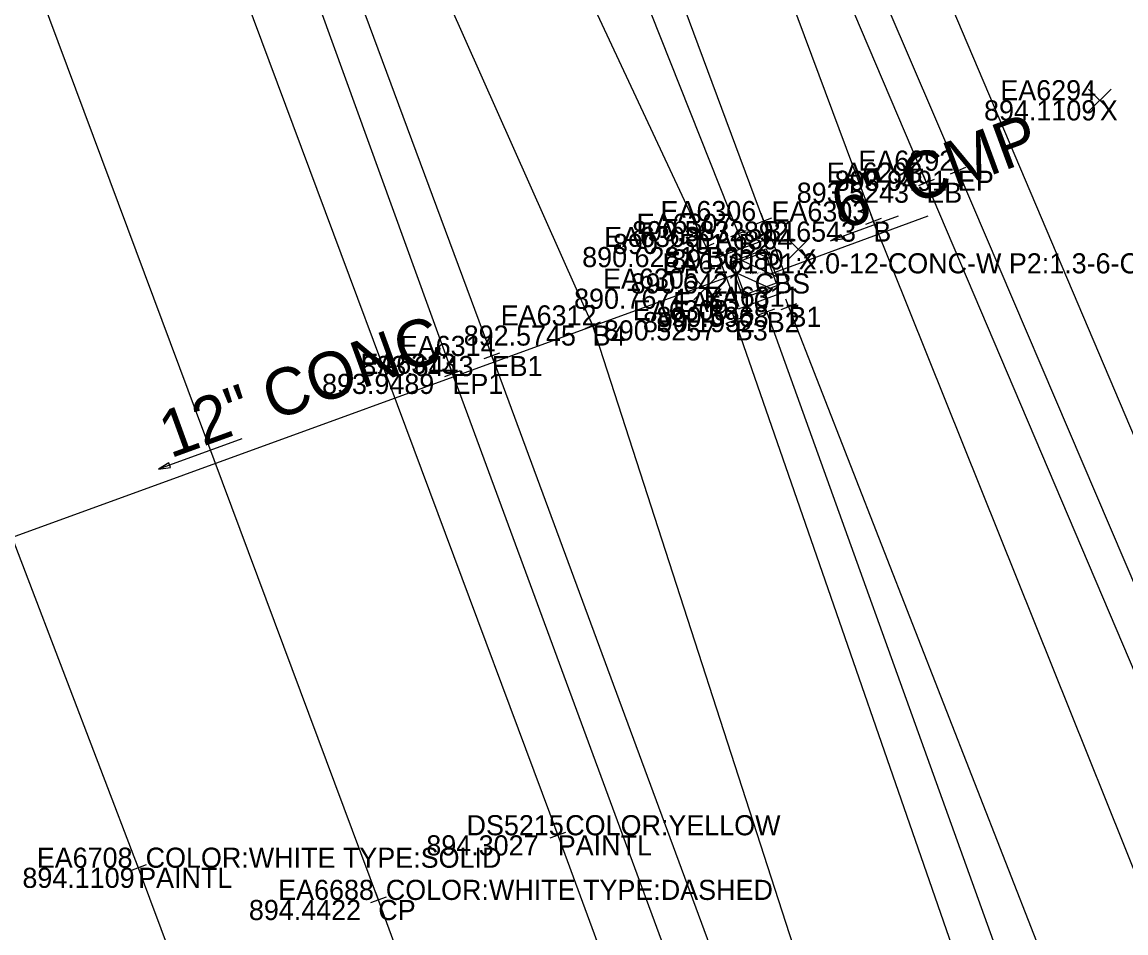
# Model space of a CAD drawing. Extents: x 179044 to 189691, y 286531 to 301257.
# Drawn here: x 180258 to 180323.8, y 300464 to 300518.4 of the extents above; entities that cross this region are included whole.
import ezdxf

# ---------------------------------------------------------------- set-up
doc = ezdxf.new("R2010")
doc.units = 0
for name, color, linetype in [('Default', 7, 'Continuous'), ('DR_X_Cells', 7, 'Continuous'), ('DR_X_Storm_Sewer', 7, 'Continuous'), ('DR_X_Text', 7, 'Continuous'), ('GK_Drainage_Nodes', 7, 'Continuous'), ('PM_X_Channelizing_Line', 7, 'Continuous'), ('PV_X_COP', 7, 'Continuous'), ('PV_X_EOP', 7, 'Continuous'), ('PV_X_Shoulder_Aggregate', 7, 'Continuous'), ('SV_X_Break_Lines', 7, 'Continuous'), ('SV_X_Random_Point', 7, 'Continuous'), ('SV_X_Shot_Marker', 7, 'Continuous'), ('SV_X_Text_Comment', 7, 'Continuous'), ('SV_X_Text_Description', 7, 'Continuous'), ('SV_X_Text_Elevation', 7, 'Continuous'), ('SV_X_Text_Name', 7, 'Continuous')]:
    doc.layers.add(name, color=color, linetype=linetype)

msp = doc.modelspace()

# ---------------------------------------------------------------- linework, layer by layer
at = {"layer": 'Default'}
for points in [[(180269.952, 300577.657), (180266.311, 300570.1), (180263.372, 300560.932), (180262.77, 300549.441), (180266.986, 300531.433), (180289.954, 300469.854), (180324.352, 300376.444), (180360.496, 300279.469), (180373.081, 300245.703)], [(180416.572, 300274.568), (180407.378, 300298.488), (180397.255, 300322.68), (180377.671, 300368.278), (180338.823, 300459.544), (180302.212, 300545.776), (180296.008, 300558.581), (180288.956, 300567.583), (180278.848, 300574.029), (180270.227, 300577.552)]]:
    msp.add_lwpolyline(points, dxfattribs=at)
at = {"layer": 'DR_X_Cells'}
for p, q in [((180300.732, 300504.228), (180302.991, 300503.187)), ((180300.732, 300504.228), (180302.991, 300503.187)), ((180301.794, 300504.62), (180302.6, 300504.248)), ((180301.794, 300504.62), (180302.6, 300504.248)), ((180300.44, 300503.482), (180302.614, 300502.48)), ((180300.44, 300503.482), (180302.614, 300502.48)), ((180300.831, 300502.421), (180301.552, 300502.088)), ((180300.831, 300502.421), (180301.552, 300502.088))]:
    msp.add_line(p, q, dxfattribs=at)
for points in [[(180302.691, 300505.506), (180303.844, 300502.378), (180300.717, 300501.225), (180299.564, 300504.352)], [(180302.691, 300505.506), (180303.844, 300502.378), (180300.717, 300501.225), (180299.564, 300504.352)], [(180302.383, 300504.837), (180303.175, 300502.687), (180301.025, 300501.894), (180300.232, 300504.044)], [(180302.383, 300504.837), (180303.175, 300502.687), (180301.025, 300501.894), (180300.232, 300504.044)], [(180302.296, 300504.65), (180302.988, 300502.773), (180301.112, 300502.081), (180300.42, 300503.958)], [(180302.296, 300504.65), (180302.988, 300502.773), (180301.112, 300502.081), (180300.42, 300503.958)]]:
    msp.add_lwpolyline(points, close=True, dxfattribs=at)
at = {"layer": 'DR_X_Storm_Sewer'}
for p, q in [((180302.704, 300503.365), (180312.049, 300506.806)), ((180300.704, 300503.365), (180226.568, 300476.391))]:
    msp.add_line(p, q, dxfattribs=at)
at = {"layer": 'DR_X_Text'}
for p, q in [((180310.249, 300506.782), (180306.226, 300505.301)), ((180271.105, 300493.5), (180266.14, 300491.694))]:
    msp.add_line(p, q, dxfattribs=at)
for points in [[(180306.831, 300505.684), (180306.935, 300505.403), (180306.226, 300505.301)], [(180266.849, 300491.792), (180266.746, 300492.074), (180266.14, 300491.694)]]:
    msp.add_lwpolyline(points, close=True, dxfattribs=at)
at = {"layer": 'GK_Drainage_Nodes'}
for p, q in [((180301.358, 300504.304), (180301.358, 300504.304)), ((180301.358, 300504.304), (180301.358, 300504.304)), ((180301.704, 300503.365), (180301.704, 300503.365)), ((180301.704, 300503.365), (180301.704, 300503.365)), ((180301.704, 300503.365), (180301.704, 300503.365)), ((180301.704, 300503.365), (180301.704, 300503.365)), ((180301.704, 300503.365), (180301.704, 300503.365)), ((180301.704, 300503.365), (180301.704, 300503.365)), ((180302.642, 300503.711), (180302.642, 300503.711)), ((180302.642, 300503.711), (180302.642, 300503.711)), ((180303.268, 300503.942), (180303.268, 300503.942)), ((180303.268, 300503.942), (180303.268, 300503.942)), ((180300.14, 300502.789), (180300.14, 300502.789)), ((180300.14, 300502.789), (180300.14, 300502.789)), ((180300.766, 300503.019), (180300.766, 300503.019)), ((180300.766, 300503.019), (180300.766, 300503.019)), ((180302.05, 300502.427), (180302.05, 300502.427)), ((180302.05, 300502.427), (180302.05, 300502.427))]:
    msp.add_line(p, q, dxfattribs=at)
at = {"layer": 'PM_X_Channelizing_Line'}
msp.add_lwpolyline([(180190.445, 300582.496), (180201.741, 300580.903), (180210.797, 300577.931), (180219.101, 300571.651), (180228.235, 300559.496), (180237.94, 300538.543), (180264.924, 300467.918), (180293.4, 300391.707), (180324.643, 300308.043), (180350.475, 300238.896)], dxfattribs=at)
at = {"layer": 'PV_X_COP'}
msp.add_lwpolyline([(180246.716, 300553.114), (180279.248, 300465.999), (180313.722, 300372.324), (180349.437, 300276.58), (180362.146, 300242.511)], dxfattribs=at)
at = {"layer": 'PV_X_EOP'}
for points in [[(180275.541, 300570.539), (180270.388, 300566.454), (180267.273, 300561.588), (180266.459, 300554.084), (180265.761, 300546.765), (180283.67, 300497.374), (180310.435, 300424.792), (180336.457, 300355.213), (180379.468, 300239.43)], [(180275.541, 300570.539), (180281.08, 300569.395), (180286.302, 300565.407), (180291.485, 300559.019), (180299.83, 300542.045), (180313.822, 300509.489), (180346.033, 300434.084), (180370.964, 300374.351), (180403.471, 300297.797), (180418.39, 300258.269)]]:
    msp.add_lwpolyline(points, dxfattribs=at)
at = {"layer": 'PV_X_Shoulder_Aggregate'}
for points in [[(180276.015, 300565.593), (180281.288, 300566.161), (180286.068, 300563.144), (180298.579, 300540.14), (180311.937, 300508.777), (180343.813, 300433.852), (180369.171, 300373.38), (180401.131, 300296.715), (180416.281, 300257.534)], [(180276.015, 300565.593), (180272.424, 300562.362), (180270.301, 300554.787), (180269.122, 300543.981), (180286.011, 300498.44), (180312.867, 300425.83), (180338.723, 300356.477), (180381.308, 300240.575)]]:
    msp.add_lwpolyline(points, dxfattribs=at)
at = {"layer": 'SV_X_Break_Lines'}
for points in [[(180285.869, 300558.023), (180297.684, 300536.245), (180308.778, 300506.456), (180338.649, 300432.1), (180367.2, 300369.993), (180410.141, 300254.681)], [(180281.085, 300555.439), (180289.69, 300533.513), (180300.73, 300505.723)], [(180284.601, 300552.482), (180292.195, 300533.463), (180302.232, 300506.484)], [(180278.676, 300551.659), (180285.337, 300533.721), (180298.804, 300504.938)], [(180274.364, 300549.595), (180277.806, 300532.178), (180292.031, 300500.259), (180315.947, 300426.336), (180343.875, 300357.803), (180387.064, 300242.808)], [(180303.72, 300501.373), (180331.456, 300430.396), (180357.818, 300364.306), (180401.637, 300249.805)], [(180302.421, 300501.058), (180327.985, 300430.042), (180355.523, 300363.079), (180398.147, 300248.566)], [(180300.517, 300500.565), (180325.39, 300428.896), (180352.275, 300361.992), (180395.375, 300246.26)]]:
    msp.add_lwpolyline(points, dxfattribs=at)
at = {"layer": 'SV_X_Random_Point'}
for p, q in [((180321.621, 300513.019), (180322.954, 300514.355)), ((180321.621, 300514.355), (180322.954, 300513.019)), ((180303.644, 300504.131), (180304.977, 300505.466)), ((180303.644, 300505.466), (180304.977, 300504.131)), ((180298.065, 300501.787), (180299.398, 300503.122)), ((180298.065, 300503.122), (180299.398, 300501.787))]:
    msp.add_line(p, q, dxfattribs=at)
at = {"layer": 'SV_X_Shot_Marker'}
for p, q in [((180313.625, 300509.948), (180314.02, 300509.03)), ((180314.282, 300509.686), (180313.363, 300509.291)), ((180313.822, 300509.489), (180313.822, 300509.489)), ((180312.397, 300508.973), (180311.477, 300508.581)), ((180311.741, 300509.237), (180312.133, 300508.317)), ((180311.937, 300508.777), (180311.937, 300508.777)), ((180302.701, 300506.658), (180301.764, 300506.309)), ((180302.058, 300506.952), (180302.407, 300506.015)), ((180309.247, 300506.63), (180308.31, 300506.281)), ((180308.604, 300506.924), (180308.953, 300505.987)), ((180300.545, 300506.187), (180300.915, 300505.258)), ((180302.232, 300506.484), (180302.232, 300506.484)), ((180308.778, 300506.456), (180308.778, 300506.456)), ((180298.592, 300505.391), (180299.015, 300504.486)), ((180301.195, 300505.907), (180300.265, 300505.538)), ((180300.73, 300505.723), (180300.73, 300505.723)), ((180299.256, 300505.15), (180298.351, 300504.727)), ((180298.804, 300504.938), (180298.804, 300504.938)), ((180302.251, 300501.529), (180302.59, 300500.588)), ((180304.186, 300501.555), (180303.254, 300501.191)), ((180303.538, 300501.839), (180303.902, 300500.908)), ((180303.72, 300501.373), (180303.72, 300501.373)), ((180291.828, 300500.716), (180292.235, 300499.803)), ((180300.989, 300500.729), (180300.045, 300500.401)), ((180300.353, 300501.038), (180300.681, 300500.093)), ((180302.891, 300501.228), (180301.95, 300500.889)), ((180302.421, 300501.058), (180302.421, 300501.058)), ((180292.488, 300500.463), (180291.575, 300500.056)), ((180292.031, 300500.259), (180292.031, 300500.259)), ((180300.517, 300500.565), (180300.517, 300500.565)), ((180285.837, 300498.909), (180286.185, 300497.971)), ((180286.48, 300498.614), (180285.542, 300498.266)), ((180286.011, 300498.44), (180286.011, 300498.44)), ((180284.14, 300497.544), (180283.2, 300497.203)), ((180283.5, 300497.844), (180283.84, 300496.904)), ((180283.67, 300497.374), (180283.67, 300497.374)), ((180290.422, 300470.028), (180289.485, 300469.679)), ((180289.779, 300470.322), (180290.129, 300469.385)), ((180289.954, 300469.854), (180289.954, 300469.854)), ((180265.391, 300468.097), (180264.457, 300467.74)), ((180264.746, 300468.385), (180265.103, 300467.451)), ((180264.924, 300467.918), (180264.924, 300467.918)), ((180279.073, 300466.467), (180279.423, 300465.53)), ((180279.717, 300466.174), (180278.78, 300465.824)), ((180279.248, 300465.999), (180279.248, 300465.999))]:
    msp.add_line(p, q, dxfattribs=at)

# ---------------------------------------------------------------- texts
at = {"layer": 'DR_X_Text'}
for s, rotation, p in [('6" CMP', 20.21069, (180306.926, 300505.932)), ('12" CONC', 19.99419, (180266.842, 300492.322))]:
    msp.add_text(s, height=2.8, rotation=rotation, dxfattribs=at).set_placement(p)
at = {"layer": 'SV_X_Text_Comment'}
for s, height, p in [('X', 1.2, (180322.288, 300512.487)), ('EP', 1.2, (180313.822, 300508.289)), ('EB', 1.2, (180311.937, 300507.577)), ('B1', 1.2, (180302.232, 300505.284)), ('B', 1.2, (180308.778, 300505.256)), ('B2', 1.2, (180300.73, 300504.523)), ('B3', 1.2, (180298.804, 300503.738)), ('X', 1.2, (180304.31, 300503.598)), ('P1=2.0-12-CONC-W P2=1.3-6-CMP-E', 0.06, (180301.704, 300503.305)), ('CBS', 1.2, (180301.704, 300502.165)), ('X', 1.2, (180298.732, 300501.254)), ('B1', 1.2, (180303.72, 300500.173)), ('B2', 1.2, (180302.421, 300499.858)), ('B4', 1.2, (180292.031, 300499.059)), ('B3', 1.2, (180300.517, 300499.365)), ('EB1', 1.2, (180286.011, 300497.24)), ('EP1', 1.2, (180283.67, 300496.174)), ('PAINTL', 1.2, (180289.954, 300468.654)), ('PAINTL', 1.2, (180264.924, 300466.718)), ('CP', 1.2, (180279.248, 300464.799))]:
    msp.add_text(s, height=height, dxfattribs=at).set_placement(p)
at = {"layer": 'SV_X_Text_Description'}
for s, height, p in [(' P1:2.0-12-CONC-W P2:1.3-6-CMP-E', 1.2, (180301.704, 300503.365)), ('P1= 2.0-12-CONC-W  P2=1.3-6-CMP-E', 0.06, (180301.704, 300503.365)), (' COLOR:YELLOW', 1.2, (180289.954, 300469.854)), (' COLOR:WHITE TYPE:SOLID', 1.2, (180264.924, 300467.918)), (' COLOR:WHITE TYPE:DASHED', 1.2, (180279.248, 300465.999))]:
    msp.add_text(s, height=height, dxfattribs=at).set_placement(p)
at = {"layer": 'SV_X_Text_Elevation'}
for s, height, p in [('894.1109', 1.2, (180315.382, 300512.487)), ('893.9491', 1.2, (180306.475, 300508.289)), ('893.5243', 1.2, (180304.209, 300507.577)), ('890.5832', 1.2, (180294.39, 300505.284)), ('892.6543', 1.2, (180301.05, 300505.256)), ('890.2501', 1.2, (180293.241, 300504.523)), ('890.6281', 1.2, (180291.409, 300503.738)), ('891.0080', 1.2, (180296.734, 300503.598)), ('890.6421', 1.2, (180294.299, 300502.165)), ('890.64', 0.06, (180301.416, 300503.305)), ('890.7674', 1.2, (180290.927, 300501.254)), ('890.5968', 1.2, (180295.84, 300500.173)), ('890.1932', 1.2, (180295.033, 300499.858)), ('892.5745', 1.2, (180284.341, 300499.059)), ('890.5257', 1.2, (180292.703, 300499.365)), ('893.6443', 1.2, (180278.235, 300497.24)), ('893.9489', 1.2, (180275.894, 300496.174)), ('894.3027', 1.2, (180282.112, 300468.654)), ('894.1109', 1.2, (180258.019, 300466.718)), ('894.4422', 1.2, (180271.529, 300464.799))]:
    msp.add_text(s, height=height, dxfattribs=at).set_placement(p)
at = {"layer": 'SV_X_Text_Name'}
for s, height, p in [('EA6294', 1.2, (180316.354, 300513.687)), ('EA6292', 1.2, (180307.889, 300509.489)), ('EA6293', 1.2, (180305.994, 300508.777)), ('EA6306', 1.2, (180296.082, 300506.484)), ('EA6303', 1.2, (180302.703, 300506.456)), ('EA6307', 1.2, (180294.655, 300505.723)), ('EA6308', 1.2, (180292.719, 300504.938)), ('EA6304', 1.2, (180298.245, 300504.798)), ('EA6261', 1.2, (180296.199, 300503.365)), ('EA6305', 1.2, (180292.657, 300502.454)), ('EA6261', 0.06, (180301.429, 300503.365)), ('EA6310', 1.2, (180296.828, 300501.058)), ('EA6311', 1.2, (180298.669, 300501.373)), ('EA6312', 1.2, (180286.552, 300500.259)), ('EA6309', 1.2, (180294.432, 300500.565)), ('EA6314', 1.2, (180280.531, 300498.44)), ('EA6313', 1.2, (180278.181, 300497.374)), ('DS5215', 1.2, (180284.512, 300469.854)), ('EA6708', 1.2, (180258.877, 300467.918)), ('EA6688', 1.2, (180273.277, 300465.999))]:
    msp.add_text(s, height=height, dxfattribs=at).set_placement(p)

doc.saveas('drawing.dxf')
